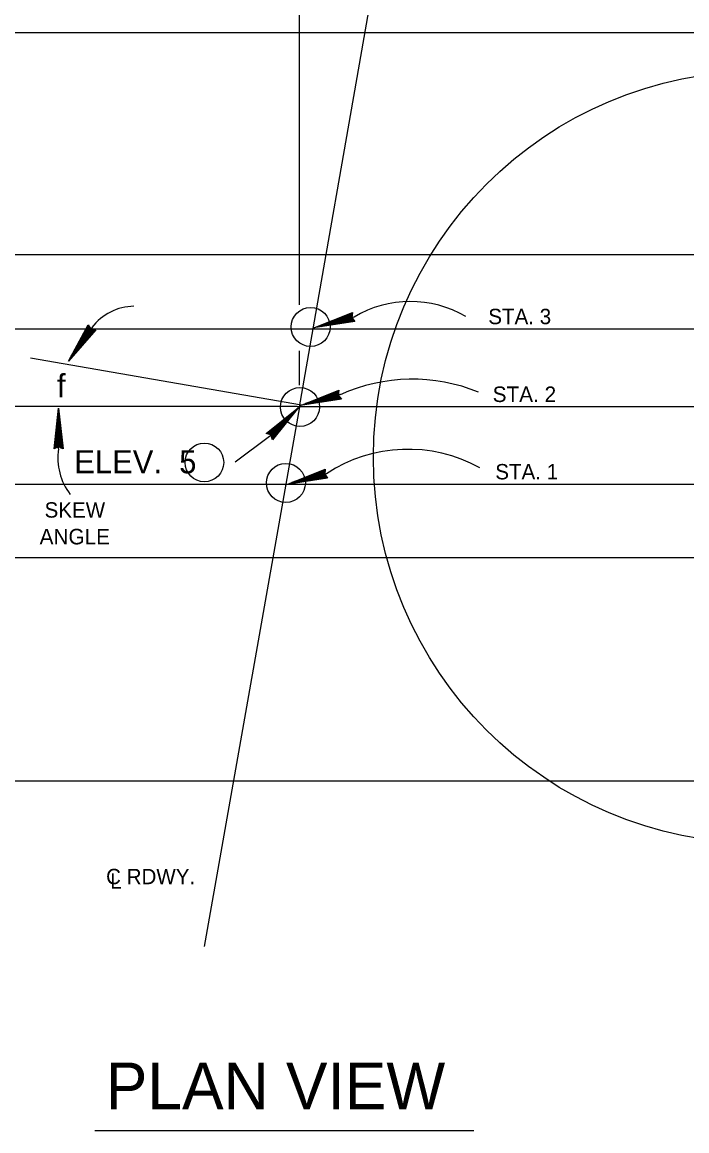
# Model space of a CAD drawing. Extents: x 1.6 to 6.29, y 2.8 to 7.08.
# Drawn here: x 3.058 to 3.414, y 6.152 to 6.747 of the extents above; entities that cross this region are included whole.
import ezdxf

# ---------------------------------------------------------------- set-up
doc = ezdxf.new("R2010")
doc.units = 0
doc.layers.add('Level 1', color=7, linetype='Continuous')
doc.layers.add('Level 5', color=7, linetype='Continuous')

msp = doc.modelspace()

# ---------------------------------------------------------------- linework, layer by layer
at = {"layer": 'Level 1'}
for p, q in [((3.20608, 6.79692), (3.20608, 6.59533)), ((3.20625, 6.54067), (3.24892, 6.7835)), ((2.80525, 6.74125), (3.60783, 6.74125)), ((2.90658, 6.62233), (3.42758, 6.62233)), ((3.21408, 6.58292), (3.23483, 6.59125)), ((3.23558, 6.58867), (3.21408, 6.58292)), ((3.21708, 6.58383), (3.23408, 6.58842)), ((3.23458, 6.59075), (3.22025, 6.58508)), ((3.23475, 6.59058), (3.22025, 6.585)), ((3.23467, 6.59033), (3.22042, 6.58467)), ((3.23483, 6.59008), (3.22042, 6.58425)), ((3.22367, 6.58542), (3.23425, 6.58942)), ((3.23425, 6.58892), (3.22367, 6.58542)), ((3.23425, 6.58808), (3.22475, 6.58542)), ((3.22658, 6.58608), (3.23425, 6.58792)), ((3.23425, 6.58792), (3.22817, 6.58625)), ((3.22817, 6.58625), (3.23458, 6.58767)), ((3.22908, 6.58758), (3.23425, 6.58892)), ((3.23408, 6.58842), (3.22908, 6.58758)), ((3.23458, 6.58767), (3.23025, 6.58633)), ((3.23425, 6.58767), (3.23383, 6.58733)), ((3.23425, 6.58942), (3.23408, 6.58808)), ((3.23408, 6.58808), (3.23533, 6.58692)), ((3.23483, 6.58708), (3.23425, 6.58767)), ((3.23433, 6.5895), (3.23458, 6.59067)), ((3.23433, 6.58842), (3.23433, 6.5895)), ((3.23433, 6.58692), (3.23433, 6.58842)), ((3.23483, 6.59125), (3.23442, 6.58842)), ((3.23442, 6.58842), (3.236, 6.58633)), ((2.71542, 6.58242), (3.6545, 6.58242)), ((3.08242, 6.565), (3.093, 6.5845)), ((3.09508, 6.58317), (3.08242, 6.565)), ((3.097, 6.58183), (3.08242, 6.565)), ((3.08392, 6.56775), (3.094, 6.58208)), ((3.09608, 6.58183), (3.08525, 6.56933)), ((3.09633, 6.58175), (3.08542, 6.56917)), ((3.0965, 6.58167), (3.0855, 6.56908)), ((3.09633, 6.58167), (3.0855, 6.56917)), ((3.093, 6.58383), (3.08567, 6.57033)), ((3.09325, 6.58383), (3.08575, 6.57033)), ((3.09342, 6.58367), (3.086, 6.57008)), ((3.09375, 6.58358), (3.08625, 6.57008)), ((3.08808, 6.57283), (3.09367, 6.58275)), ((3.09383, 6.58242), (3.08808, 6.57283)), ((3.09433, 6.58183), (3.08875, 6.57358)), ((3.08975, 6.57517), (3.0945, 6.58175)), ((3.09542, 6.58167), (3.09058, 6.57558)), ((3.09083, 6.57808), (3.09383, 6.58242)), ((3.094, 6.58208), (3.09083, 6.57808)), ((3.0945, 6.58175), (3.09108, 6.57633)), ((3.09108, 6.57633), (3.095, 6.58167)), ((3.095, 6.58167), (3.09242, 6.57792)), ((3.09242, 6.57792), (3.09542, 6.58167)), ((3.093, 6.5845), (3.09442, 6.58225)), ((3.09375, 6.58292), (3.093, 6.58383)), ((3.09367, 6.58275), (3.09425, 6.58175)), ((3.09425, 6.58208), (3.09375, 6.58292)), ((3.09533, 6.58108), (3.09425, 6.58208)), ((3.09425, 6.58175), (3.09608, 6.58167)), ((3.09442, 6.58225), (3.097, 6.58183)), ((3.09458, 6.58158), (3.0945, 6.58108)), ((3.09558, 6.5815), (3.09458, 6.58158)), ((3.09608, 6.58167), (3.09558, 6.5815)), ((3.236, 6.58633), (3.21408, 6.58292)), ((3.2195, 6.585), (3.21708, 6.58383)), ((3.22725, 6.586), (3.21775, 6.58367)), ((3.21775, 6.58367), (3.2195, 6.585)), ((3.2355, 6.58708), (3.21925, 6.58458)), ((3.23558, 6.58683), (3.21925, 6.58425)), ((3.23558, 6.58667), (3.21925, 6.584)), ((3.23558, 6.58675), (3.21933, 6.58408)), ((3.23558, 6.58658), (3.21933, 6.584)), ((3.22475, 6.58542), (3.22483, 6.58575)), ((3.22483, 6.58575), (3.22658, 6.58608)), ((3.23492, 6.58733), (3.22725, 6.586)), ((3.23025, 6.58633), (3.23492, 6.58733)), ((3.23383, 6.58733), (3.23433, 6.58692)), ((3.23533, 6.58692), (3.23483, 6.58708)), ((3.0965, 6.5815), (3.08567, 6.56908)), ((3.0945, 6.58108), (3.09533, 6.58108)), ((3.08533, 6.56992), (3.08392, 6.56775)), ((3.09058, 6.57558), (3.08467, 6.56808)), ((3.08467, 6.56808), (3.08533, 6.56992)), ((3.08867, 6.57375), (3.08975, 6.57517)), ((3.08875, 6.57358), (3.08867, 6.57375)), ((3.20608, 6.57067), (3.20608, 6.55225)), ((3.20692, 6.54125), (3.22733, 6.5495)), ((3.22833, 6.54717), (3.20692, 6.54125)), ((3.20958, 6.54233), (3.22658, 6.54692)), ((3.22717, 6.54908), (3.21283, 6.5435)), ((3.22733, 6.54883), (3.21283, 6.54333)), ((3.22725, 6.54858), (3.213, 6.54308)), ((3.22733, 6.54842), (3.213, 6.54283)), ((3.21625, 6.54375), (3.22675, 6.54783)), ((3.22675, 6.54733), (3.21625, 6.54375)), ((3.22675, 6.54658), (3.21733, 6.54375)), ((3.21925, 6.54442), (3.22675, 6.5465)), ((3.22675, 6.5465), (3.22075, 6.5445)), ((3.22075, 6.5445), (3.22708, 6.54625)), ((3.22158, 6.54608), (3.22675, 6.54733)), ((3.22658, 6.54692), (3.22158, 6.54608)), ((3.22708, 6.54625), (3.22275, 6.54467)), ((3.22675, 6.54625), (3.22633, 6.54567)), ((3.22675, 6.54783), (3.22667, 6.54658)), ((3.22667, 6.54658), (3.22817, 6.54517)), ((3.22733, 6.54533), (3.22675, 6.54625)), ((3.22683, 6.54517), (3.22692, 6.54692)), ((3.22692, 6.54783), (3.22708, 6.549)), ((3.22692, 6.54692), (3.22692, 6.54783)), ((3.22733, 6.5495), (3.227, 6.54692)), ((3.227, 6.54692), (3.22883, 6.54467)), ((3.20508, 6.54075), (2.70767, 6.54075)), ((3.20625, 6.54067), (3.15517, 6.25125)), ((3.18842, 6.52633), (3.20583, 6.54025)), ((3.19025, 6.52467), (3.20583, 6.54025)), ((3.20583, 6.54025), (3.19183, 6.52283)), ((3.20508, 6.54075), (3.6545, 6.54075)), ((3.22883, 6.54467), (3.20692, 6.54125)), ((3.21217, 6.54333), (3.20958, 6.54233)), ((3.22008, 6.54425), (3.21042, 6.54225)), ((3.21042, 6.54225), (3.21217, 6.54333)), ((3.22825, 6.54533), (3.21183, 6.543)), ((3.22833, 6.54508), (3.21183, 6.54283)), ((3.22842, 6.545), (3.21183, 6.54258)), ((3.22833, 6.54508), (3.21192, 6.54258)), ((3.22833, 6.54483), (3.21192, 6.54258)), ((3.21733, 6.54408), (3.21925, 6.54442)), ((3.21733, 6.54375), (3.21733, 6.54408)), ((3.22758, 6.54567), (3.22008, 6.54425)), ((3.22275, 6.54467), (3.22758, 6.54567)), ((3.22633, 6.54567), (3.22683, 6.54517)), ((3.22817, 6.54517), (3.22733, 6.54533)), ((3.07467, 6.518), (3.07708, 6.53992)), ((3.07483, 6.5185), (3.07675, 6.53483)), ((3.075, 6.5185), (3.07683, 6.53483)), ((3.07508, 6.5185), (3.07683, 6.53483)), ((3.07508, 6.5185), (3.077, 6.53483)), ((3.07542, 6.51833), (3.07717, 6.53483)), ((3.0765, 6.52658), (3.07692, 6.53625)), ((3.07692, 6.53625), (3.07758, 6.53433)), ((3.07708, 6.518), (3.07708, 6.53992)), ((3.07708, 6.53992), (3.07958, 6.518)), ((3.07758, 6.53433), (3.07733, 6.53692)), ((3.07733, 6.53692), (3.07742, 6.5195)), ((3.189, 6.52658), (3.20192, 6.53683)), ((3.189, 6.5265), (3.202, 6.53683)), ((3.189, 6.52633), (3.20208, 6.53675)), ((3.18917, 6.52633), (3.20208, 6.53667)), ((3.18925, 6.52617), (3.20225, 6.53642)), ((3.20383, 6.53817), (3.19142, 6.52558)), ((3.19142, 6.52392), (3.20117, 6.53592)), ((3.19158, 6.52383), (3.20125, 6.53583)), ((3.19183, 6.52367), (3.2015, 6.53558)), ((3.19192, 6.5235), (3.20158, 6.53558)), ((3.19583, 6.53117), (3.20308, 6.53792)), ((3.20208, 6.53592), (3.20383, 6.53817)), ((3.20308, 6.53792), (3.20208, 6.53592)), ((3.07683, 6.5195), (3.07675, 6.52933)), ((3.07675, 6.52933), (3.07692, 6.52933)), ((3.0785, 6.51833), (3.07683, 6.53375)), ((3.07775, 6.51925), (3.07683, 6.5305)), ((3.07683, 6.5305), (3.07808, 6.51917)), ((3.07692, 6.52933), (3.07683, 6.52733)), ((3.07875, 6.51833), (3.07708, 6.53375)), ((3.079, 6.5185), (3.07742, 6.53383)), ((3.07908, 6.5185), (3.07758, 6.53383)), ((3.19008, 6.52625), (3.19583, 6.53117)), ((3.19367, 6.52958), (3.19008, 6.52625)), ((3.19533, 6.53067), (3.19058, 6.52608)), ((3.19058, 6.52608), (3.19367, 6.52958)), ((3.19667, 6.5315), (3.19092, 6.52608)), ((3.19092, 6.52608), (3.19533, 6.53067)), ((3.191, 6.52592), (3.19792, 6.533)), ((3.19142, 6.52525), (3.19883, 6.53367)), ((3.19142, 6.52558), (3.19525, 6.52908)), ((3.19525, 6.52908), (3.19142, 6.52525)), ((3.19883, 6.53367), (3.19158, 6.52483)), ((3.19808, 6.53283), (3.19667, 6.5315)), ((3.19792, 6.533), (3.19808, 6.53283)), ((3.07592, 6.51908), (3.0765, 6.52658)), ((3.07617, 6.52392), (3.07592, 6.51908)), ((3.07642, 6.51925), (3.07617, 6.52392)), ((3.0765, 6.52583), (3.07642, 6.51925)), ((3.07675, 6.5195), (3.0765, 6.52583)), ((3.07683, 6.52733), (3.07675, 6.5195)), ((3.07742, 6.5195), (3.07775, 6.52467)), ((3.07775, 6.52467), (3.07775, 6.51925)), ((3.191, 6.52558), (3.18842, 6.52633)), ((3.18933, 6.52633), (3.19, 6.5265)), ((3.19117, 6.52592), (3.18933, 6.52633)), ((3.19, 6.5265), (3.19083, 6.52625)), ((3.191, 6.52667), (3.19033, 6.52683)), ((3.19033, 6.52683), (3.19117, 6.52558)), ((3.19083, 6.52625), (3.191, 6.52667)), ((3.19183, 6.52283), (3.191, 6.52558)), ((3.19158, 6.52483), (3.19117, 6.52592)), ((3.19117, 6.52558), (3.1915, 6.52467)), ((3.1915, 6.52467), (3.19192, 6.52358)), ((3.07708, 6.51917), (3.07467, 6.518)), ((3.07683, 6.51958), (3.07542, 6.51858)), ((3.07542, 6.51858), (3.07567, 6.51917)), ((3.07617, 6.52025), (3.07558, 6.51967)), ((3.07558, 6.51967), (3.07717, 6.51942)), ((3.07567, 6.51917), (3.0765, 6.51958)), ((3.0765, 6.51958), (3.07617, 6.52025)), ((3.07808, 6.51917), (3.07683, 6.51958)), ((3.07958, 6.518), (3.07708, 6.51917)), ((3.07717, 6.51942), (3.07808, 6.519)), ((3.07808, 6.519), (3.07908, 6.5185)), ((3.1995, 6.499), (3.22017, 6.50725)), ((3.22083, 6.50475), (3.1995, 6.499)), ((3.20225, 6.5), (3.21933, 6.5045)), ((3.21992, 6.50667), (3.20542, 6.50108)), ((3.22008, 6.50658), (3.20542, 6.50092)), ((3.22008, 6.50625), (3.20558, 6.50067)), ((3.22017, 6.50608), (3.20558, 6.50033)), ((3.20883, 6.50142), (3.2195, 6.50533)), ((3.2195, 6.50492), (3.20883, 6.50142)), ((3.21408, 6.50367), (3.2195, 6.50492)), ((3.21933, 6.5045), (3.21408, 6.50367)), ((3.2195, 6.50533), (3.21942, 6.50417)), ((3.2195, 6.503), (3.21975, 6.5045)), ((3.21975, 6.50542), (3.21983, 6.50667)), ((3.21975, 6.5045), (3.21975, 6.50542)), ((3.22017, 6.50725), (3.21983, 6.5045)), ((3.21983, 6.5045), (3.22133, 6.50233)), ((2.7135, 6.49917), (3.65008, 6.49917)), ((3.22133, 6.50233), (3.1995, 6.499)), ((3.20475, 6.50092), (3.20225, 6.5)), ((3.21258, 6.50192), (3.20308, 6.49983)), ((3.20308, 6.49983), (3.20475, 6.50092)), ((3.22083, 6.50308), (3.20442, 6.50058)), ((3.22083, 6.50283), (3.20442, 6.50033)), ((3.221, 6.50275), (3.20442, 6.50008)), ((3.22083, 6.50275), (3.2045, 6.50017)), ((3.22083, 6.50242), (3.2045, 6.50008)), ((3.2195, 6.50417), (3.20992, 6.50142)), ((3.20992, 6.50142), (3.21, 6.50167)), ((3.21, 6.50167), (3.21183, 6.50208)), ((3.21183, 6.50208), (3.2195, 6.50408)), ((3.22025, 6.50333), (3.21258, 6.50192)), ((3.2195, 6.50408), (3.21333, 6.50217)), ((3.21333, 6.50217), (3.21983, 6.50383)), ((3.21983, 6.50383), (3.21558, 6.50233)), ((3.21558, 6.50233), (3.22025, 6.50333)), ((3.2195, 6.50383), (3.219, 6.50333)), ((3.219, 6.50333), (3.2195, 6.503)), ((3.21942, 6.50417), (3.22075, 6.503)), ((3.22017, 6.50308), (3.2195, 6.50383)), ((3.22075, 6.503), (3.22017, 6.50308)), ((2.90658, 6.45975), (3.43333, 6.45975)), ((3.60783, 6.33992), (2.80525, 6.33992)), ((3.29975, 6.15233), (3.09658, 6.15233))]:
    msp.add_line(p, q, dxfattribs=at)
for centre, radius in [((3.45306, 6.51361), 0.20706), ((3.21227, 6.58344), 0.01045), ((3.20655, 6.54049), 0.01045), ((3.1553, 6.51077), 0.01036), ((3.199, 6.49978), 0.01045)]:
    msp.add_circle(centre, radius, dxfattribs=at)
at = {"layer": 'Level 5'}
for p, q in [((3.20742, 6.5415), (3.06208, 6.56675)), ((3.19025, 6.52467), (3.17175, 6.511))]:
    msp.add_line(p, q, dxfattribs=at)
for centre, radius, start, end in [((3.11792, 6.5657), 0.02883, 90.76421, 142.70243), ((3.26582, 6.53809), 0.05897, 59.64297, 120.83185), ((3.26687, 6.46111), 0.09428, 67.84713, 114.20121), ((3.10825, 6.51306), 0.03156, 170.99053, 217.99721), ((3.26444, 6.43869), 0.07914, 60.84448, 123.43193)]:
    msp.add_arc(centre, radius, start, end, dxfattribs=at)

# ---------------------------------------------------------------- texts
at = {"layer": 'Level 1'}
for s, height, p in [('STA. 3', 0.00825, (3.30758, 6.58492)), ('f ', 0.012416, (3.07617, 6.54567)), ('STA. 2', 0.008333, (3.30992, 6.54317)), ('STA. 1', 0.00825, (3.31133, 6.50167)), ('SKEW', 0.00825, (3.06958, 6.48117)), ('ANGLE', 0.008333, (3.06692, 6.46683)), ('C RDWY.', 0.008249, (3.10258, 6.28458)), ('L', 0.00833, (3.10475, 6.28217)), ('PLAN VIEW', 0.025, (3.10242, 6.16392))]:
    msp.add_text(s, height=height, dxfattribs=at).set_placement(p)
at = {"layer": 'Level 5'}
msp.add_text('ELEV.  5', height=0.012417, dxfattribs=at).set_placement((3.0855, 6.50492))

doc.saveas('drawing.dxf')
